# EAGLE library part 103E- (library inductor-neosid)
FILTER triple helix bandpass filter, type E
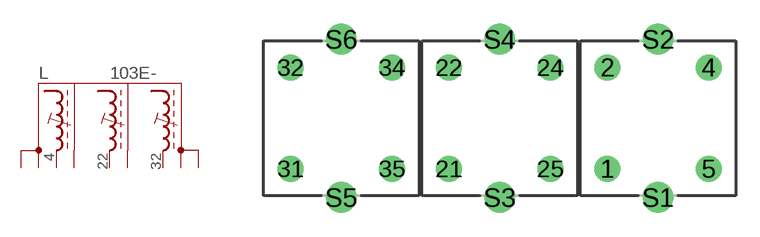
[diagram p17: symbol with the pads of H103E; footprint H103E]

Designator prefix L

## 103E-42232 (OC_FARNELL: unknown; OC_NEWARK: unknown)  [H103E]
4  IN  pas
22  GND2  pas
32  OUT1  pas
S1  S1  pas
S2  S2  pas
S3  S3  pas
S4  S4  pas
S5  S5  pas
S6  S6  pas

## 103E-22232 (OC_FARNELL: unknown; OC_NEWARK: unknown)  [H103E]
2  IN  pas
22  GND2  pas
32  OUT1  pas
S1  S1  pas
S2  S2  pas
S3  S3  pas
S4  S4  pas
S5  S5  pas
S6  S6  pas

## Footprint H103E (pad centres in mm)
TRIPLE RF COIL ASSEMBLY 10.1, 4 pads, grid 2.5, 10 x 10 x 15 mm
drill 1.1 round: 1 6.8,-3.45; 2 6.8,2.95; 4 13.2,2.95; 5 13.2,-3.45; 21 -3.2,-3.45; 22 -3.2,2.95; 24 3.2,2.95; 25 3.2,-3.45; 31 -13.2,-3.45; 32 -13.2,2.95; 34 -6.8,2.95; 35 -6.8,-3.45
drill 1.3 round: S1 10,-5.25; S2 10,4.75; S3 0,-5.25; S4 0,4.75; S5 -10,-5.25; S6 -10,4.75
